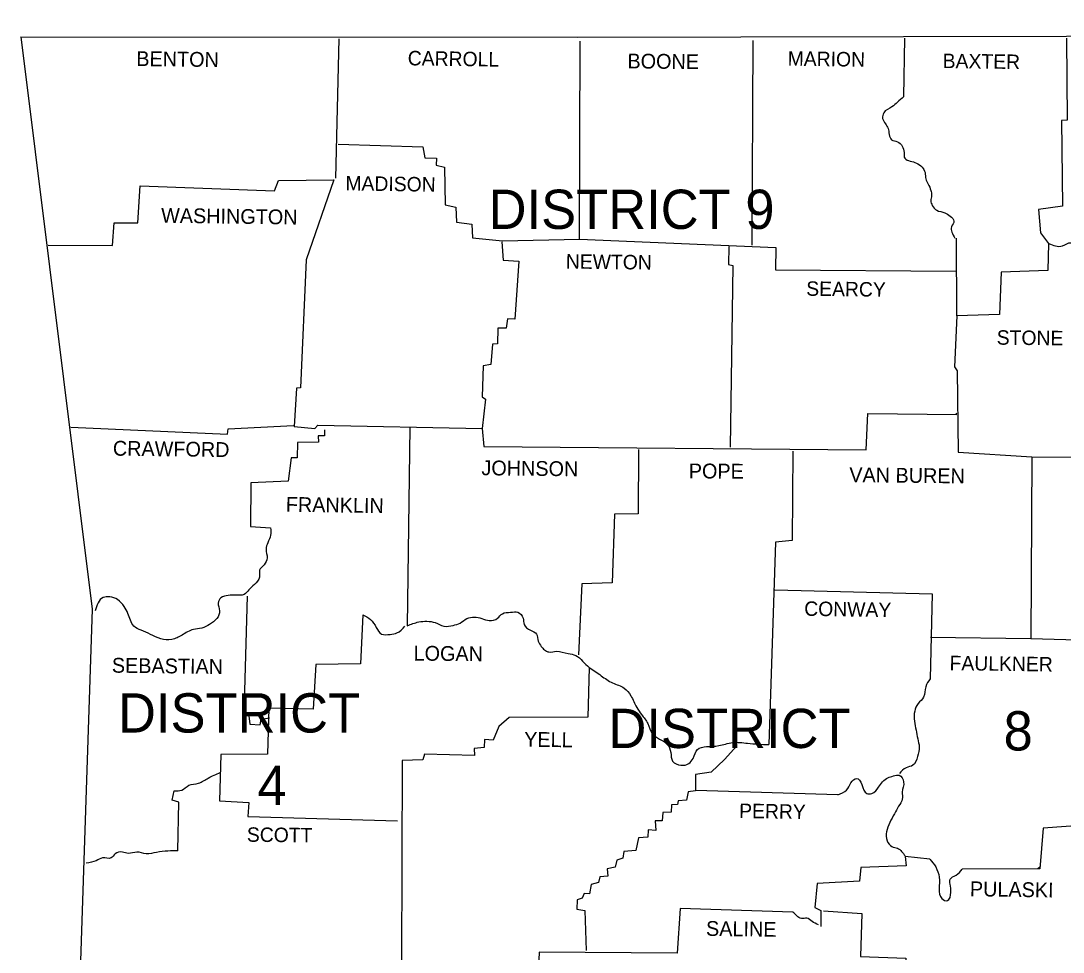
# Model space of a CAD drawing. Extents: x 155 to 3386, y 68 to 2138.
# Drawn here: x 2703.7 to 2999.8, y 1696.4 to 1960.9 of the extents above; entities that cross this region are included whole.
import ezdxf

# ---------------------------------------------------------------- set-up
doc = ezdxf.new("R2010")
doc.units = 0
for name, color, linetype in [('1', 7, 'Continuous'), ('2', 7, 'Continuous'), ('3', 7, 'Continuous')]:
    doc.layers.add(name, color=color, linetype=linetype)

msp = doc.modelspace()

# ---------------------------------------------------------------- linework, layer by layer
at = {"layer": '1'}
for points in [[(2703.71, 1956.42), (2861.92, 1956.32), (3000.75, 1956.61), (3164.54, 1959.16), (3240.46, 1960.92)], [(2703.71, 1956.42), (2723.96, 1793.81), (2715.15, 1528.37)], [(2794.01, 1955.83), (2793.13, 1916.21)], [(2793.82, 1925.89), (2817.89, 1925.11), (2818.47, 1921.98), (2821.8, 1921.88), (2821.7, 1919.92), (2824.05, 1919.34), (2824.25, 1908.67), (2827.28, 1907.99), (2827.48, 1903.78), (2831.78, 1903.19), (2831.98, 1899.28), (2840.49, 1898.4), (2862.4, 1898.89), (2862.6, 1955.15)], [(2911.62, 1955.34), (2911.33, 1897.22)], [(2954.67, 1956.03), (2954.47, 1939.3)], [(3000.75, 1956.03), (3000.95, 1932.74), (2999.28, 1932.64), (2999.58, 1908.28), (2992.73, 1907.3), (2993.32, 1900.75), (2995.66, 1897.71), (2995.47, 1889.98), (2982.16, 1889.5), (2981.67, 1877.56), (2969.54, 1877.17), (2968.95, 1862.69), (2969.64, 1861.51), (2969.93, 1838.42), (2990.87, 1837.05), (2990.58, 1785.49), (3007.21, 1785), (3007.21, 1732.56), (2994.1, 1731.58), (2993.12, 1720.04), (2971.11, 1719.94)], [(2711.44, 1897.22), (2729.73, 1897.13), (2730.22, 1903.58), (2736.97, 1903.58), (2737.56, 1914.05), (2775.72, 1912.68), (2776.89, 1915.62), (2792.64, 1915.72), (2784.72, 1893.02), (2783.15, 1856.72), (2781.98, 1856.62), (2781.39, 1845.66), (2787.17, 1845.17), (2788.05, 1846.05), (2834.72, 1845.17), (2835.21, 1839.99)], [(2840.29, 1898.2), (2840.68, 1892.92), (2845.18, 1892.63), (2844.01, 1876.19), (2841.96, 1876.29), (2841.56, 1873.65), (2839.22, 1873.65), (2839.12, 1869.14), (2837.65, 1869.05), (2837.16, 1863.27), (2835.01, 1862.98), (2834.72, 1854.17), (2835.69, 1853.49), (2834.72, 1845.17)], [(2862.4, 1898.89), (2918.17, 1896.54), (2918.08, 1890.18), (2969.25, 1889.79)], [(2969.54, 1877.17), (2969.44, 1899.18)], [(2904.77, 1896.83), (2904.67, 1891.75), (2905.94, 1891.45), (2905.16, 1839.79)], [(2835.21, 1839.99), (2943.81, 1839.11), (2944.3, 1849.38), (2969.54, 1849.09)], [(2969.25, 1849.19), (2969.54, 1849.48)], [(2717.89, 1845.56), (2762.41, 1843.51), (2762.61, 1845.08), (2781.2, 1845.96)], [(2790, 1844.78), (2790, 1843.02), (2788.14, 1843.02), (2788.24, 1841.26), (2782.27, 1841.16), (2782.18, 1836.76), (2780.51, 1836.76), (2779.63, 1830.2), (2769.06, 1829.71), (2768.97, 1817.29), (2774.64, 1816.9)], [(2814.17, 1845.56), (2813.48, 1789.11)], [(2879.14, 1839.21), (2879.04, 1820.91), (2872.29, 1820.81), (2871.7, 1801.34), (2863.09, 1801.05), (2862.11, 1780.89)], [(2922.97, 1838.72), (2922.77, 1813.28), (2918.08, 1812.89), (2916.22, 1755.36)], [(2990.87, 1837.05), (3041.16, 1836.76), (3045.46, 1838.81), (3045.17, 1800.56), (3042.24, 1799.29), (3039.59, 1797.04), (3038.71, 1796.16), (3038.62, 1785.2), (3006.62, 1785.2)], [(2767.99, 1797.53), (2767.01, 1763.87), (2768.48, 1763.48), (2768.77, 1761.13), (2771.71, 1760.93), (2772, 1762.6), (2774.35, 1762.99)], [(2917.88, 1799.29), (2962.59, 1798.21), (2962.01, 1774.04)], [(2800.86, 1792.24), (2800.18, 1778.25), (2787.46, 1778.15), (2786.77, 1765.43), (2774.15, 1765.73), (2773.76, 1752.62), (2760.55, 1752.52), (2760.16, 1739.41), (2768.48, 1738.92), (2768.18, 1734.91), (2810.65, 1733.73)], [(2962.1, 1785.88), (2990.58, 1785.49)], [(2865.14, 1777.27), (2864.75, 1763.18), (2842.45, 1763.09), (2839.51, 1760.54), (2837.85, 1756.63), (2835.4, 1756.82), (2835.3, 1754.57), (2832.47, 1754.28), (2832.56, 1752.22), (2818.38, 1752.62), (2817.89, 1751.05), (2812.02, 1750.86), (2811.82, 1693.62)], [(2907.12, 1754.96), (2903.6, 1751.15), (2899.78, 1747.53), (2895.38, 1746.84), (2895.38, 1742.25), (2893.22, 1741.95), (2892.83, 1739.6), (2890.39, 1739.41), (2890.19, 1738.33), (2888.53, 1738.23), (2888.43, 1736.18), (2886.08, 1736.08), (2885.89, 1733.73), (2883.93, 1733.73), (2884.03, 1730.99), (2881.88, 1731.19), (2881.78, 1729.04), (2879.14, 1728.84), (2878.35, 1725.32), (2875.03, 1725.03), (2874.73, 1723.07), (2872.97, 1722.58), (2872.48, 1720.52), (2870.23, 1720.04), (2870.43, 1717.98), (2868.18, 1717.78), (2867.79, 1716.22), (2865.73, 1715.63), (2865.24, 1712.99), (2863.68, 1713.09), (2863.19, 1711.72), (2861.72, 1711.23), (2861.62, 1708.59), (2863.87, 1708.2), (2864.26, 1696.85)], [(2748.32, 1725.22), (2748.62, 1739.02), (2746.66, 1739.6), (2747.25, 1742.25)], [(2935.79, 1741.07), (2895.47, 1742.34)], [(2961.91, 1722.77), (2954.86, 1723.56), (2955.16, 1720.92), (2942.34, 1720.43), (2941.95, 1716.61), (2929.91, 1715.93), (2929.23, 1709.08), (2930.99, 1708.2), (2930.99, 1703.7)], [(2992.63, 1720.13), (2993.12, 1720.62)], [(2922.97, 1707.81), (2890.97, 1708.78), (2890.09, 1696.16), (2850.96, 1696.36), (2850.76, 1692.15)], [(2931.68, 1708.1), (2942.63, 1707.41), (2942.24, 1695.18), (2955.06, 1694.69), (2955.26, 1684.03), (2961.32, 1683.54), (2961.32, 1681.68), (2967, 1681.29), (2967.19, 1674.44), (2980.11, 1674.44), (2980.5, 1667.69), (2992.44, 1667.1), (2992.34, 1654.38)]]:
    msp.add_lwpolyline(points, dxfattribs=at)
for points in [[(2954.47, 1939.3), (2952.71, 1937.83), (2951.15, 1936.46), (2948.8, 1934.8), (2948.5, 1933.23), (2949.29, 1931.66), (2950.07, 1930.39), (2950.36, 1928.63), (2951.05, 1927.16), (2952.71, 1926.58), (2954.08, 1925.31), (2954.57, 1923.54), (2954.77, 1921.88), (2956.33, 1921.1), (2958.09, 1920.51), (2959.76, 1919.34), (2960.54, 1917.87), (2960.73, 1916.01), (2961.42, 1914.54), (2962.2, 1912.78), (2962.4, 1911.31), (2962.2, 1909.85), (2962.59, 1908.48), (2963.87, 1907.11), (2966.12, 1906.42), (2967.68, 1905.44), (2968.76, 1904.07), (2968.07, 1902.41), (2968.17, 1900.94), (2969.05, 1899.18)], [(2995.66, 1897.71), (2999.58, 1897.03), (3001.93, 1897.91), (3003.59, 1895.37), (3004.47, 1893.41), (3005.94, 1890.57), (3008.29, 1889.69), (3010.05, 1888.13), (3010.05, 1886.46), (3008.48, 1884.9), (3007.31, 1883.33), (3007.7, 1881.47), (3008.09, 1878.93), (3008.09, 1876.48), (3007.5, 1874.23), (3007.01, 1872.18), (3007.5, 1870.42), (3009.36, 1870.71), (3011.32, 1872.18), (3013.37, 1872.18), (3015.33, 1871.1), (3017.38, 1869.24), (3019.44, 1869.63), (3021.1, 1870.12), (3023.45, 1870.81), (3025.11, 1869.93), (3026.58, 1868.75), (3028.34, 1866.89), (3030.01, 1865.72), (3032.16, 1864.64), (3034.8, 1863.96), (3037.25, 1862.3), (3037.64, 1859.46), (3037.54, 1857.01), (3037.34, 1853.98), (3037.15, 1850.65), (3037.44, 1847.42), (3038.52, 1845.27), (3039.89, 1842.73), (3040.28, 1840.38), (3040.18, 1836.66)], [(2774.64, 1816.9), (2774.64, 1814.84), (2773.86, 1812.69), (2773.37, 1810.83), (2773.66, 1808.39), (2772.78, 1806.43), (2771.51, 1804.86), (2771.51, 1802.91), (2770.04, 1800.85), (2768.48, 1799.29), (2767.11, 1798.01), (2764.66, 1797.82), (2762.61, 1797.72), (2760.55, 1797.04), (2759.77, 1795.57), (2760.16, 1793.32), (2759.38, 1791.17), (2757.32, 1789.5), (2755.07, 1788.43), (2752.73, 1788.03), (2749.5, 1786.47), (2746.56, 1785.2), (2743.43, 1785.39), (2740.5, 1786.66), (2737.85, 1787.84), (2735.8, 1789.01), (2734.14, 1792.63), (2733.06, 1794.59), (2731.2, 1796.55), (2728.95, 1797.33), (2727.09, 1797.13), (2724.84, 1793.32)], [(2800.86, 1792.24), (2803.02, 1790.87), (2804.68, 1788.62), (2806.15, 1786.76), (2808.59, 1786.66), (2810.55, 1787.06), (2812.8, 1789.01)], [(2813.48, 1789.11), (2816.71, 1790.19), (2819.06, 1790.38), (2821.41, 1789.99), (2823.86, 1789.01), (2826.5, 1789.21), (2828.45, 1789.89), (2830.41, 1791.17), (2832.56, 1791.56), (2834.62, 1791.17), (2836.77, 1790.58), (2839.12, 1791.26), (2840.49, 1792.54), (2842.84, 1792.93), (2844.89, 1792.93), (2846.36, 1791.26), (2846.65, 1789.5), (2848.51, 1787.84), (2850.17, 1786.76), (2850.66, 1784.71), (2851.54, 1783.24), (2852.43, 1782.26), (2853.7, 1781.67), (2855.85, 1781.87), (2859.18, 1781.19), (2861.33, 1780.7), (2863.29, 1779.03), (2865.14, 1777.27)], [(2865.14, 1777.27), (2868.57, 1774.92), (2871.8, 1772.87), (2875.12, 1771.4), (2876.98, 1769.25), (2878.65, 1765.92), (2880.02, 1763.87), (2881.78, 1761.32), (2883.05, 1758.49), (2885.1, 1756.92), (2887.26, 1755.55), (2888.33, 1753.11), (2888.82, 1750.66), (2891.17, 1749.49), (2893.42, 1749.97), (2894.69, 1751.44), (2895.87, 1753.99), (2898.51, 1754.77), (2901.93, 1755.06), (2905.85, 1755.94), (2910.15, 1755.75), (2916.22, 1755.36)], [(2962.01, 1774.04), (2960.73, 1771.79), (2960.15, 1768.86), (2958.58, 1767), (2957.6, 1764.85), (2957.51, 1762.01), (2958, 1759.47), (2958.48, 1757.02), (2958.88, 1754.77), (2958.39, 1751.93), (2957.11, 1749.49), (2955.16, 1748.8), (2953.3, 1747.14)], [(2747.25, 1742.25), (2749.4, 1742.44), (2751.45, 1743.81), (2754.19, 1744.4), (2756.93, 1745.87), (2760.36, 1747.43)], [(2935.79, 1741.07), (2938.23, 1742.44), (2939.5, 1744.5), (2941.07, 1745.77), (2942.63, 1744.01), (2944, 1741.46), (2945.47, 1741.46), (2947.33, 1743.22), (2948.5, 1744.79), (2949.97, 1745.96), (2951.54, 1746.45), (2953.2, 1746.65), (2954.47, 1744.79), (2954.08, 1741.85), (2954.08, 1739.9), (2953.01, 1737.84), (2951.83, 1735.69), (2950.56, 1733.24), (2949.58, 1730.6), (2949.78, 1728.06), (2951.15, 1726.39), (2952.71, 1725.91), (2954.86, 1723.75)], [(2748.32, 1725.22), (2745.49, 1725.12), (2742.26, 1724.73), (2739.32, 1724.34), (2736.68, 1724.83), (2734.23, 1724.44), (2732.57, 1724.83), (2730.52, 1724.34), (2729.34, 1723.17), (2726.9, 1723.17), (2725.13, 1722.38), (2722.3, 1721.7)], [(2961.91, 1722.77), (2963.57, 1720.62), (2964.55, 1717.69), (2964.55, 1714.36), (2965.33, 1711.62), (2966.9, 1711.03), (2967.88, 1713.38), (2967.68, 1715.73), (2967.68, 1717.1), (2969.34, 1718.27), (2971.11, 1719.94)], [(2930.31, 1704.19), (2928.45, 1705.16), (2926.98, 1706.04), (2925.41, 1705.95), (2924.14, 1706.73), (2922.97, 1707.81)]]:
    msp.add_spline(points, degree=3, dxfattribs=at)

# ---------------------------------------------------------------- texts
at = {"layer": '2'}
for s, height, rotation, p in [('BENTON', 4.207, 359.2527, (2736.48, 1948.1)), ('CARROLL', 4.109, 359.1481, (2813.58, 1948.3)), ('BOONE', 4.207, 359.4001, (2876, 1947.42)), ('MARION', 4.109, 359.1854, (2921.5, 1948.2)), ('BAXTER', 4.109, 359.2559, (2965.53, 1947.51)), ('MADISON', 4.109, 359.0906, (2795.87, 1912.78)), ('WASHINGTON', 4.206, 359.232, (2743.53, 1903.58)), ('NEWTON', 4.109, 359.2717, (2858.49, 1890.57)), ('SEARCY', 4.108, 359.2527, (2926.78, 1882.84)), ('STONE', 4.108, 359.4001, (2980.89, 1868.95)), ('CRAWFORD', 4.206, 359.2771, (2729.83, 1837.44)), ('JOHNSON', 4.207, 359.3514, (2834.52, 1831.87)), ('POPE', 4.207, 359.6155, (2893.42, 1830.99)), ('VAN BUREN', 4.207, 359.3508, (2939.01, 1829.91)), ('FRANKLIN', 4.207, 359.1815, (2778.95, 1821.5)), ('CONWAY', 4.108, 359.0371, (2926.2, 1791.95)), ('LOGAN', 4.207, 359.3969, (2815.25, 1779.23)), ('SEBASTIAN', 4.206, 359.2816, (2729.54, 1775.8)), ('FAULKNER', 4.109, 359.2486, (2967.49, 1776.49)), ('YELL', 4.207, 359.1987, (2846.65, 1754.77)), ('PERRY', 4.109, 359.0858, (2907.71, 1734.52)), ('SCOTT', 4.109, 359.4063, (2767.89, 1727.76)), ('PULASKI', 4.207, 359.053, (2973.26, 1712.31)), ('SALINE', 4.207, 359.1491, (2898.31, 1701.05))]:
    msp.add_text(s, height=height, rotation=rotation, dxfattribs=at).set_placement(p)
at = {"layer": '3'}
for s, height, p in [('DISTRICT 9', 11.154, (2836.57, 1901.82)), ('DISTRICT', 11.154, (2731.3, 1758.78)), ('DISTRICT', 11.154, (2870.62, 1754.38)), ('8', 11.15, (2982.85, 1753.69)), ('4', 11.15, (2770.92, 1738.23))]:
    msp.add_text(s, height=height, dxfattribs=at).set_placement(p)

doc.saveas('drawing.dxf')
